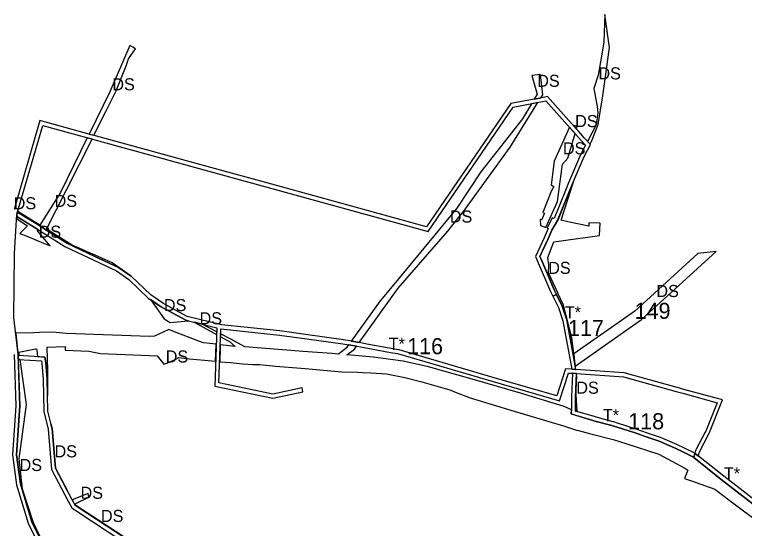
# Model space of a CAD drawing. Extents: x -477304 to -465641, y -1159113 to -1149285.
# Drawn here: x -471593 to -471049, y -1153715 to -1153332 of the extents above; entities that cross this region are included whole.
import ezdxf

# ---------------------------------------------------------------- set-up
doc = ezdxf.new("R2010")
doc.units = 0
for name, color, linetype in [('14', 7, 'Continuous'), ('35', 7, 'Continuous'), ('4', 7, 'Continuous'), ('60', 7, 'Continuous')]:
    doc.layers.add(name, color=color, linetype=linetype)

msp = doc.modelspace()

# ---------------------------------------------------------------- linework, layer by layer
at = {"layer": '14'}
for p, q in [((-471070.39, -1153508.62), (-471083.94, -1153510.15)), ((-471175.31, -1153593.86), (-471175.29, -1153593.96))]:
    msp.add_line(p, q, dxfattribs=at)
for points in [[(-471175.29, -1153593.96), (-471125.97, -1153559.31), (-471070.39, -1153508.62)], [(-471083.94, -1153510.15), (-471130.99, -1153553.06), (-471176.35, -1153584.93)], [(-471176.35, -1153584.93), (-471175.69, -1153590.63), (-471175.31, -1153593.86)]]:
    msp.add_lwpolyline(points, dxfattribs=at)
at = {"layer": '35'}
for p, q in [((-471153.26, -1153332.25), (-471153.87, -1153352.54)), ((-471504.57, -1153356.6), (-471506.78, -1153355.15)), ((-471502.61, -1153357.86), (-471504.57, -1153356.6)), ((-471153.87, -1153352.54), (-471155.75, -1153363.3)), ((-471507.84, -1153365.29), (-471502.61, -1153357.86)), ((-471509.71, -1153370.34), (-471507.84, -1153365.29)), ((-471155.75, -1153363.3), (-471158.23, -1153377.45)), ((-471517.12, -1153389.03), (-471509.71, -1153370.34)), ((-471201.13, -1153376.92), (-471207.63, -1153377.64)), ((-471199.47, -1153391.91), (-471201.13, -1153376.92)), ((-471158.23, -1153377.45), (-471161.5, -1153387.25)), ((-471524.62, -1153404.35), (-471517.12, -1153389.03)), ((-471161.5, -1153387.25), (-471158.95, -1153400.81)), ((-471200.93, -1153394.26), (-471199.47, -1153391.91)), ((-471158.17, -1153414.21), (-471154.66, -1153392.72)), ((-471223.64, -1153430.89), (-471203.08, -1153397.73)), ((-471207.77, -1153398.64), (-471214.42, -1153409.84)), ((-471203.08, -1153397.73), (-471207.77, -1153398.64)), ((-471533.59, -1153422.16), (-471524.62, -1153404.35)), ((-471158.56, -1153405.29), (-471159.57, -1153414.43)), ((-471158.95, -1153400.81), (-471158.56, -1153405.29)), ((-471214.42, -1153409.84), (-471245.64, -1153449.35)), ((-471179.62, -1153416.07), (-471190.85, -1153441.33)), ((-471175.29, -1153420.9), (-471179.62, -1153416.07)), ((-471173.71, -1153415.61), (-471176.9, -1153414.6)), ((-471174.28, -1153417.53), (-471173.71, -1153415.61)), ((-471159.57, -1153414.43), (-471166.1, -1153426.66)), ((-471162.56, -1153425.49), (-471158.17, -1153414.21)), ((-471180.7, -1153439.05), (-471175.29, -1153420.9)), ((-471538.53, -1153423.92), (-471558.53, -1153464.67)), ((-471554.05, -1153462.8), (-471534.97, -1153424.9)), ((-471534.97, -1153424.9), (-471538.53, -1153423.92)), ((-471166.1, -1153426.66), (-471164.23, -1153428.75)), ((-471164.23, -1153428.75), (-471162.56, -1153425.49)), ((-471259.06, -1153479.59), (-471223.64, -1153430.89)), ((-471190.85, -1153441.33), (-471193.1, -1153459.06)), ((-471245.64, -1153449.35), (-471263.3, -1153476.38)), ((-471193.1, -1153459.06), (-471191.15, -1153460.17)), ((-471185.8, -1153485.31), (-471176.64, -1153456.89)), ((-471558.53, -1153464.67), (-471573.79, -1153489.04)), ((-471568.84, -1153492.14), (-471554.05, -1153462.8)), ((-471192.84, -1153463.23), (-471199.39, -1153479.58)), ((-471191.15, -1153460.17), (-471192.84, -1153463.23)), ((-471197.19, -1153490.88), (-471188.35, -1153471.52)), ((-471590.35, -1153478.87), (-471590.48, -1153479.34)), ((-471573.79, -1153489.04), (-471590.35, -1153478.87)), ((-471263.3, -1153476.38), (-471304.47, -1153526.09)), ((-471261.88, -1153483.13), (-471259.06, -1153479.59)), ((-471198.19, -1153480.08), (-471200.35, -1153485.34)), ((-471199.39, -1153479.58), (-471198.19, -1153480.08)), ((-471591, -1153482.55), (-471591.11, -1153484.39)), ((-471591.11, -1153484.39), (-471583.17, -1153489.5)), ((-471581.05, -1153488.71), (-471591, -1153482.55)), ((-471270.21, -1153493.58), (-471261.88, -1153483.13)), ((-471200.35, -1153485.34), (-471201.46, -1153484.88)), ((-471201.46, -1153484.88), (-471201.19, -1153489.33)), ((-471188.38, -1153485.63), (-471192.58, -1153492.66)), ((-471188.02, -1153484.75), (-471188.38, -1153485.63)), ((-471180.84, -1153486.55), (-471185.8, -1153485.31)), ((-471165.11, -1153489.74), (-471180.84, -1153486.55)), ((-471583.17, -1153489.5), (-471588.75, -1153495.17)), ((-471578.21, -1153490.47), (-471581.05, -1153488.71)), ((-471575.38, -1153492.25), (-471578.21, -1153490.47)), ((-471575.65, -1153493.28), (-471575.38, -1153492.25)), ((-471563.06, -1153495.82), (-471568.84, -1153492.14)), ((-471201.19, -1153489.33), (-471197.19, -1153490.88)), ((-471165.07, -1153487.35), (-471165.11, -1153489.74)), ((-471156.76, -1153487.53), (-471165.07, -1153487.35)), ((-471157.24, -1153496.84), (-471156.76, -1153487.53)), ((-471588.75, -1153495.17), (-471584.16, -1153497.07)), ((-471584.16, -1153497.07), (-471571.1, -1153502.48)), ((-471566.24, -1153504.49), (-471575.65, -1153493.28)), ((-471306.99, -1153535.86), (-471270.21, -1153493.58)), ((-471192.58, -1153492.66), (-471195.75, -1153499.62)), ((-471191.32, -1153501.42), (-471157.24, -1153496.84)), ((-471571.1, -1153502.48), (-471566.24, -1153504.49)), ((-471195.75, -1153499.62), (-471199.01, -1153506.75)), ((-471195.66, -1153513.24), (-471191.32, -1153501.42)), ((-471199.01, -1153506.75), (-471199.12, -1153506.98)), ((-471519.92, -1153517.09), (-471530.34, -1153512.46)), ((-471194.82, -1153518.49), (-471195.66, -1153513.24)), ((-471515.1, -1153520.51), (-471519.92, -1153517.09)), ((-471195.1, -1153524.61), (-471194.82, -1153518.49)), ((-471515.43, -1153520.57), (-471505.82, -1153527.09)), ((-471505.82, -1153527.09), (-471515.1, -1153520.51)), ((-471336.16, -1153576.5), (-471306.99, -1153535.86)), ((-471484.13, -1153549.53), (-471491.47, -1153544.52)), ((-471491.47, -1153544.52), (-471481.37, -1153558.81)), ((-471320.48, -1153545.29), (-471342.04, -1153575.43)), ((-471463.31, -1153560.3), (-471465.24, -1153559.82)), ((-471453.1, -1153562.85), (-471458.88, -1153561.41)), ((-471458.88, -1153561.41), (-471442.28, -1153570.5)), ((-471442.21, -1153568.49), (-471453.1, -1153562.85)), ((-471477.72, -1153566.83), (-471482.16, -1153568.86)), ((-471473.7, -1153568.51), (-471477.72, -1153566.83)), ((-471455.45, -1153575.44), (-471473.7, -1153568.51)), ((-471442.28, -1153570.5), (-471442.21, -1153568.49)), ((-471591.55, -1153569.41), (-471591.83, -1153569.43)), ((-471591.83, -1153569.43), (-471590.72, -1153579.53)), ((-471578.22, -1153569.23), (-471591.55, -1153569.41)), ((-471574.11, -1153568.99), (-471578.22, -1153569.23)), ((-471564.11, -1153568.73), (-471574.11, -1153568.99)), ((-471488.44, -1153571.73), (-471492.17, -1153571.99)), ((-471482.16, -1153568.86), (-471488.44, -1153571.73)), ((-471439.26, -1153570.01), (-471439.33, -1153572.11)), ((-471439.33, -1153572.11), (-471432.63, -1153575.78)), ((-471431.66, -1153573.95), (-471439.26, -1153570.01)), ((-471421.37, -1153579.58), (-471431.66, -1153573.95)), ((-471452, -1153576.75), (-471455.45, -1153575.44)), ((-471442.53, -1153577.78), (-471452, -1153576.75)), ((-471442.97, -1153590.42), (-471442.53, -1153577.78)), ((-471439.54, -1153578.11), (-471439.64, -1153580.84)), ((-471428.45, -1153579.32), (-471439.54, -1153578.11)), ((-471432.63, -1153575.78), (-471428.45, -1153579.32)), ((-471343.97, -1153578.13), (-471346.01, -1153580.98)), ((-471339.68, -1153581.4), (-471338.1, -1153579.2)), ((-471590.72, -1153579.53), (-471590.45, -1153582.02)), ((-471590.45, -1153582.02), (-471590.11, -1153585.11)), ((-471589.41, -1153583.6), (-471577.2, -1153581.09)), ((-471589.04, -1153586.18), (-471589.41, -1153583.6)), ((-471577.2, -1153581.09), (-471576.29, -1153581.03)), ((-471576.29, -1153581.03), (-471576.17, -1153582.12)), ((-471576.17, -1153582.12), (-471575.62, -1153586.97)), ((-471568.43, -1153579.98), (-471555.04, -1153579.46)), ((-471568.08, -1153589.04), (-471568.43, -1153579.98)), ((-471555.04, -1153579.46), (-471554.94, -1153582.13)), ((-471554.94, -1153582.13), (-471537.39, -1153582.98)), ((-471537.39, -1153582.98), (-471528.59, -1153584.53)), ((-471528.59, -1153584.53), (-471486.48, -1153586.34)), ((-471439.64, -1153580.84), (-471439.98, -1153590.72)), ((-471380.68, -1153582.86), (-471421.37, -1153579.58)), ((-471351.53, -1153585.11), (-471356.21, -1153584.75)), ((-471346.01, -1153580.98), (-471351.53, -1153585.11)), ((-471345.28, -1153585.59), (-471339.68, -1153581.4)), ((-471590.11, -1153585.11), (-471590.07, -1153586.12)), ((-471590.07, -1153586.12), (-471589.04, -1153586.18)), ((-471588.61, -1153589.21), (-471589.96, -1153589.13)), ((-471583.88, -1153622.53), (-471588.61, -1153589.21)), ((-471575.62, -1153586.97), (-471570.07, -1153587.3)), ((-471568, -1153596.67), (-471568.08, -1153589.04)), ((-471486.48, -1153586.34), (-471482.43, -1153591.38)), ((-471478.59, -1153591.7), (-471473.22, -1153589.05)), ((-471473.22, -1153589.05), (-471470.42, -1153587.67)), ((-471470.42, -1153587.67), (-471468.44, -1153587.91)), ((-471468.44, -1153587.91), (-471465.15, -1153588.23)), ((-471465.15, -1153588.23), (-471442.97, -1153590.42)), ((-471339.25, -1153586.05), (-471345.28, -1153585.59)), ((-471325.69, -1153587.36), (-471339.25, -1153586.05)), ((-471176.89, -1153585.31), (-471175.31, -1153593.86)), ((-471482.43, -1153591.38), (-471481.55, -1153592.48)), ((-471481.55, -1153592.48), (-471478.59, -1153591.7)), ((-471422.87, -1153592.2), (-471418.94, -1153592.57)), ((-471418.94, -1153592.57), (-471415.32, -1153592.9)), ((-471415.32, -1153592.9), (-471414.51, -1153592.9)), ((-471405.47, -1153593.3), (-471398.45, -1153593.94)), ((-471567.92, -1153610.69), (-471568, -1153596.67)), ((-471337.21, -1153598.64), (-471333.54, -1153598.74)), ((-471333.54, -1153598.74), (-471327.39, -1153598.92)), ((-471327.39, -1153598.92), (-471315.85, -1153599.85)), ((-471215.99, -1153614.15), (-471251.89, -1153603.85)), ((-471174.44, -1153601.37), (-471174.96, -1153617.12)), ((-471567.99, -1153614.18), (-471567.92, -1153610.69)), ((-471568.15, -1153615.86), (-471567.99, -1153614.18)), ((-471183.59, -1153624.05), (-471215.99, -1153614.15)), ((-471174.96, -1153617.12), (-471175.11, -1153627.46)), ((-471173.82, -1153627.84), (-471174.45, -1153615.52)), ((-471228.08, -1153625.33), (-471192.33, -1153636.01)), ((-471178.13, -1153626.62), (-471183.59, -1153624.05)), ((-471178.26, -1153629.66), (-471178.13, -1153626.62)), ((-471175.11, -1153627.46), (-471173.82, -1153627.84)), ((-471174.55, -1153630.75), (-471178.26, -1153629.66)), ((-471159.57, -1153635.15), (-471174.55, -1153630.75)), ((-471564.59, -1153640.68), (-471565.66, -1153636.94)), ((-471565.66, -1153636.94), (-471564.82, -1153640.44)), ((-471192.33, -1153636.01), (-471183.91, -1153638.52)), ((-471183.91, -1153638.52), (-471174.22, -1153641.64)), ((-471562.25, -1153669.67), (-471564.59, -1153640.68)), ((-471164.59, -1153644.16), (-471147.02, -1153648.7)), ((-471147.02, -1153648.7), (-471137.68, -1153651.55)), ((-471137.68, -1153651.55), (-471112.96, -1153659.6)), ((-471078.02, -1153669.2), (-471086.84, -1153662.19)), ((-471553.94, -1153685.69), (-471562.25, -1153669.67)), ((-471091.36, -1153671.49), (-471093.87, -1153677.66)), ((-471093.87, -1153677.66), (-471088.67, -1153679.47)), ((-471088.67, -1153679.47), (-471071.33, -1153685.71)), ((-471553.32, -1153687), (-471553.94, -1153685.69)), ((-471071.33, -1153685.71), (-471059.91, -1153694.3)), ((-471537.84, -1153688.93), (-471549.78, -1153693.66)), ((-471548.12, -1153696.77), (-471537.36, -1153691.52)), ((-471537.36, -1153691.52), (-471537.84, -1153688.93)), ((-471549.78, -1153693.66), (-471548.12, -1153696.77)), ((-471511.99, -1153720.59), (-471547.83, -1153697.31)), ((-471547.83, -1153697.31), (-471547.69, -1153697.57)), ((-471059.91, -1153694.3), (-471032.64, -1153714.82)), ((-471558.34, -1153753.04), (-471578.48, -1153710.75))]:
    msp.add_line(p, q, dxfattribs=at)
for points in [[(-471154.66, -1153392.72), (-471149.87, -1153356.83), (-471153.26, -1153332.25)], [(-471506.78, -1153355.15), (-471521.74, -1153389.71), (-471537.18, -1153421.18)], [(-471207.63, -1153377.64), (-471203.49, -1153391.44), (-471205.72, -1153395.19)], [(-471205.72, -1153395.19), (-471201.53, -1153394.38), (-471200.93, -1153394.26)], [(-471176.9, -1153414.6), (-471175.99, -1153415.63), (-471174.28, -1153417.53)], [(-471537.18, -1153421.18), (-471536.3, -1153421.42), (-471533.59, -1153422.16)], [(-471188.35, -1153471.52), (-471184.67, -1153443.61), (-471180.7, -1153439.05)], [(-471176.64, -1153456.89), (-471177.43, -1153458.78), (-471179.72, -1153464.27), (-471188.02, -1153484.75)], [(-471590.48, -1153479.34), (-471576.62, -1153487.93), (-471568.23, -1153493.2), (-471562.91, -1153496.55), (-471556.64, -1153500.5), (-471553.72, -1153502.34), (-471532.82, -1153512.29), (-471515.43, -1153520.57)], [(-471530.34, -1153512.46), (-471549.69, -1153503.87), (-471563.06, -1153495.82)], [(-471199.12, -1153506.98), (-471201.58, -1153512.37), (-471200.75, -1153514.29), (-471190.89, -1153537.26), (-471189.19, -1153540.74)], [(-471187.91, -1153540.12), (-471188.18, -1153539.53), (-471195.1, -1153524.61)], [(-471304.47, -1153526.09), (-471316.58, -1153540.62), (-471320.48, -1153545.29)], [(-471189.19, -1153540.74), (-471185.02, -1153549.35), (-471181.64, -1153559.49), (-471176.89, -1153585.31)], [(-471176.35, -1153584.93), (-471177.79, -1153572.61), (-471183.99, -1153548.58), (-471187.91, -1153540.12)], [(-471465.24, -1153559.82), (-471484.01, -1153549.63), (-471484.13, -1153549.53)], [(-471481.37, -1153558.81), (-471476.72, -1153561.65), (-471463.31, -1153560.3)], [(-471492.17, -1153571.99), (-471554.18, -1153569.65), (-471564.11, -1153568.73)], [(-471338.1, -1153579.2), (-471343.75, -1153578.17), (-471343.97, -1153578.13)], [(-471342.04, -1153575.43), (-471341.63, -1153575.51), (-471336.16, -1153576.5)], [(-471356.21, -1153584.75), (-471378.13, -1153583.06), (-471380.68, -1153582.86)], [(-471589.96, -1153589.13), (-471588.75, -1153623.57), (-471591.27, -1153660.08), (-471588.26, -1153681.79), (-471579.89, -1153709.91), (-471557.48, -1153755.17)], [(-471570.07, -1153587.3), (-471569.49, -1153591.61), (-471568.41, -1153603.49), (-471568.15, -1153615.86)], [(-471251.89, -1153603.85), (-471284.42, -1153594.65), (-471303.31, -1153590.35), (-471325.69, -1153587.36)], [(-471175.31, -1153593.86), (-471175.69, -1153590.63), (-471176.35, -1153584.93)], [(-471439.98, -1153590.72), (-471439.33, -1153590.78), (-471431.82, -1153591.35), (-471422.87, -1153592.2)], [(-471414.51, -1153592.9), (-471410.01, -1153592.89), (-471405.47, -1153593.3)], [(-471398.45, -1153593.94), (-471379.39, -1153595.66), (-471376.33, -1153595.92)], [(-471376.33, -1153595.92), (-471349.03, -1153598.31), (-471337.21, -1153598.64)], [(-471315.85, -1153599.85), (-471302.08, -1153602.43), (-471289.45, -1153605.83), (-471268.75, -1153611.78)], [(-471174.45, -1153615.52), (-471174.34, -1153602.22), (-471174.44, -1153601.37)], [(-471268.75, -1153611.78), (-471265.26, -1153613.13), (-471253.48, -1153617.65), (-471233.99, -1153623.54), (-471228.08, -1153625.33)], [(-471578.48, -1153710.75), (-471586.74, -1153685.53), (-471589.38, -1153663.17), (-471583.88, -1153622.53)], [(-471086.84, -1153662.19), (-471087.49, -1153661.67), (-471087.7, -1153661.51), (-471094.68, -1153658.13), (-471100.89, -1153655.14), (-471112.75, -1153650.03), (-471122.39, -1153646.69), (-471130.7, -1153643.81), (-471144.79, -1153639.28), (-471147.4, -1153638.45), (-471147.97, -1153638.27), (-471159.57, -1153635.15)], [(-471564.82, -1153640.44), (-471562.33, -1153670.06), (-471553.32, -1153687)], [(-471174.22, -1153641.64), (-471172.85, -1153642.08), (-471164.59, -1153644.16)], [(-471112.96, -1153659.6), (-471093.61, -1153669.94), (-471091.36, -1153671.49)], [(-471022.56, -1153711.6), (-471028.57, -1153707.74), (-471066.5, -1153678.36), (-471078.02, -1153669.2)], [(-471547.69, -1153697.57), (-471545.36, -1153699.1), (-471510.88, -1153721.69), (-471503.72, -1153722.88)]]:
    msp.add_lwpolyline(points, dxfattribs=at)
at = {"layer": '4'}
for p, q in [((-471590.89, -1153480.85), (-471591, -1153482.55)), ((-471590.89, -1153480.76), (-471590.89, -1153480.85)), ((-471192.58, -1153492.66), (-471188.38, -1153485.63)), ((-471195.38, -1153491.58), (-471198.48, -1153498.37)), ((-471195.75, -1153499.62), (-471192.58, -1153492.66)), ((-471189.19, -1153540.74), (-471191.89, -1153542.05)), ((-471191.89, -1153542.05), (-471189.19, -1153540.74)), ((-471191.89, -1153542.05), (-471187.8, -1153550.48)), ((-471438.61, -1153563.36), (-471464.14, -1153557.01)), ((-471465.24, -1153559.82), (-471442.11, -1153565.58)), ((-471439.13, -1153566.33), (-471395.52, -1153570.85)), ((-471395.21, -1153567.86), (-471438.61, -1153563.36)), ((-471590.07, -1153586.12), (-471589.96, -1153589.13)), ((-471175.31, -1153593.86), (-471176.89, -1153585.31)), ((-471174.82, -1153596.56), (-471175.31, -1153593.86)), ((-471182.54, -1153596.05), (-471188.94, -1153616.26)), ((-471180.39, -1153599.2), (-471177.37, -1153599.39)), ((-471177.9, -1153596.35), (-471175, -1153596.54)), ((-471177.37, -1153599.39), (-471174.38, -1153599.59)), ((-471174.38, -1153599.59), (-471177.37, -1153599.39)), ((-471175, -1153596.54), (-471174.82, -1153596.56)), ((-471174.96, -1153617.12), (-471174.38, -1153599.59)), ((-471174.38, -1153599.59), (-471139.38, -1153601.89)), ((-471378.05, -1153613.08), (-471378.68, -1153610.15)), ((-471175.11, -1153627.46), (-471174.96, -1153617.12)), ((-471178.26, -1153629.66), (-471159.57, -1153635.15)), ((-471086.38, -1153660.19), (-471086.84, -1153662.19)), ((-471086.84, -1153662.19), (-471086.38, -1153660.19)), ((-471086.1, -1153658.95), (-471086.38, -1153660.19)), ((-471086.38, -1153660.19), (-471086.1, -1153658.95)), ((-471085.63, -1153659.32), (-471086.1, -1153658.95)), ((-471083.49, -1153661.02), (-471085.63, -1153659.32))]:
    msp.add_line(p, q, dxfattribs=at)
for points in [[(-471163.97, -1153429.04), (-471168.57, -1153423.91), (-471171.39, -1153420.76), (-471172.87, -1153419.1), (-471175.99, -1153415.63), (-471195.98, -1153393.3), (-471197.92, -1153393.68), (-471201.53, -1153394.38), (-471223.27, -1153398.58), (-471286, -1153490.27), (-471401.07, -1153458.62), (-471436.72, -1153448.81), (-471532.55, -1153422.45), (-471536.3, -1153421.42), (-471573.82, -1153411.1), (-471593.07, -1153477.49)], [(-471518.29, -1153956.42), (-471540.25, -1153885.85), (-471527.35, -1153830.76), (-471528.58, -1153824.83), (-471547.09, -1153784.31), (-471550.09, -1153776.39), (-471556.65, -1153756.83), (-471579.89, -1153709.91), (-471588.26, -1153681.79), (-471591.27, -1153660.08), (-471588.75, -1153623.57), (-471590.11, -1153585.11), (-471593.12, -1153557.74), (-471592.67, -1153510.14), (-471590.89, -1153480.85), (-471590.89, -1153480.76), (-471571.76, -1153414.78), (-471284.73, -1153493.73), (-471221.49, -1153401.29), (-471197.08, -1153396.57), (-471170.8, -1153425.91), (-471167.61, -1153429.48)], [(-471167.61, -1153429.48), (-471171.44, -1153436.65), (-471180.2, -1153457.63), (-471182.49, -1153463.13), (-471190.96, -1153484.02)], [(-471188.38, -1153485.63), (-471179.72, -1153464.27), (-471177.43, -1153458.78), (-471168.73, -1153437.94), (-471163.97, -1153429.04)], [(-471515.43, -1153520.57), (-471532.82, -1153512.29), (-471553.72, -1153502.34), (-471556.64, -1153500.5), (-471562.91, -1153496.55), (-471568.23, -1153493.2), (-471576.62, -1153487.93), (-471590.48, -1153479.34), (-471590.89, -1153480.76)], [(-471591, -1153482.55), (-471578.21, -1153490.47), (-471574.01, -1153493.12), (-471555.17, -1153504.97), (-471516.92, -1153523.18)], [(-471190.96, -1153484.02), (-471192.48, -1153483.64), (-471196.13, -1153491.29), (-471195.38, -1153491.58)], [(-471198.48, -1153498.37), (-471204.86, -1153512.33), (-471203.51, -1153515.47), (-471193.62, -1153538.51), (-471191.89, -1153542.05)], [(-471189.19, -1153540.74), (-471190.89, -1153537.26), (-471200.75, -1153514.29), (-471201.58, -1153512.37), (-471195.75, -1153499.62)], [(-471516.92, -1153523.18), (-471507.71, -1153529.43), (-471493.15, -1153543.37), (-471484.13, -1153549.53)], [(-471482.27, -1153547.17), (-471491.25, -1153541.03), (-471505.82, -1153527.09), (-471515.43, -1153520.57)], [(-471176.89, -1153585.31), (-471181.64, -1153559.49), (-471185.02, -1153549.35), (-471189.19, -1153540.74)], [(-471484.13, -1153549.53), (-471484.01, -1153549.63), (-471465.24, -1153559.82)], [(-471464.14, -1153557.01), (-471467.3, -1153555.29), (-471482.27, -1153547.17)], [(-471187.8, -1153550.48), (-471184.55, -1153560.24), (-471177.9, -1153596.35)], [(-471442.11, -1153565.58), (-471443.61, -1153609), (-471400.38, -1153617.93), (-471378.05, -1153613.08)], [(-471378.68, -1153610.15), (-471400.39, -1153614.87), (-471440.53, -1153606.58), (-471439.13, -1153566.33)], [(-471188.94, -1153616.26), (-471235.56, -1153602.63), (-471306.4, -1153581.92), (-471306.81, -1153581.8), (-471330.3, -1153577.56), (-471335.95, -1153576.53), (-471341.63, -1153575.51), (-471347.71, -1153574.41), (-471374.31, -1153570.74), (-471395.17, -1153567.87), (-471395.21, -1153567.86)], [(-471395.52, -1153570.85), (-471375.15, -1153573.66), (-471348.18, -1153577.37), (-471343.75, -1153578.17), (-471337.99, -1153579.22), (-471332.35, -1153580.23), (-471312.85, -1153583.76), (-471307.5, -1153584.72), (-471236.4, -1153605.51), (-471186.96, -1153619.97), (-471180.39, -1153599.2)], [(-471593.1, -1153585.33), (-471591.75, -1153623.52), (-471594.28, -1153660.18), (-471591.2, -1153682.43), (-471582.69, -1153711.01), (-471559.43, -1153757.98), (-471552.92, -1153777.4), (-471549.86, -1153785.47), (-471531.45, -1153825.77), (-471530.42, -1153830.72), (-471543.35, -1153885.97), (-471540.91, -1153893.83), (-471539.22, -1153899.26), (-471538.44, -1153901.74), (-471522.52, -1153952.94)], [(-471443.2, -1153802.96), (-471447.93, -1153796.05), (-471486.59, -1153739.57), (-471497.31, -1153723.94), (-471510.88, -1153721.69), (-471545.36, -1153699.1), (-471547.69, -1153697.57), (-471550.03, -1153693.18), (-471562.33, -1153670.06), (-471564.82, -1153640.44), (-471567.91, -1153627.54), (-471568.41, -1153603.49), (-471569.49, -1153591.61), (-471570.07, -1153587.3), (-471590.07, -1153586.12)], [(-471589.96, -1153589.13), (-471572.71, -1153590.15), (-471572.47, -1153591.95), (-471571.41, -1153603.66), (-471570.9, -1153627.92), (-471567.79, -1153640.92), (-471565.27, -1153670.93), (-471552.68, -1153694.59), (-471549.98, -1153699.66), (-471547.01, -1153701.61), (-471511.99, -1153724.55), (-471499.06, -1153726.69), (-471489.07, -1153741.27), (-471450.41, -1153797.74), (-471445.68, -1153804.65)], [(-471083.49, -1153661.02), (-471082.8, -1153657.97), (-471075.7, -1153644.56), (-471075.27, -1153643.48), (-471065.56, -1153619.23), (-471094.33, -1153611.37), (-471099.33, -1153609.95), (-471138.87, -1153598.92), (-471174.82, -1153596.56), (-471175, -1153596.54), (-471177.9, -1153596.35), (-471182.54, -1153596.05)], [(-471177.37, -1153599.39), (-471177.96, -1153617.05), (-471178.08, -1153625.46), (-471178.26, -1153629.66)], [(-471139.38, -1153601.89), (-471100.14, -1153612.84), (-471095.14, -1153614.26), (-471069.6, -1153621.24), (-471078.06, -1153642.37), (-471078.43, -1153643.3), (-471085.64, -1153656.92), (-471086.1, -1153658.95)], [(-471086.1, -1153658.95), (-471093.38, -1153655.43), (-471099.64, -1153652.41), (-471111.66, -1153647.23), (-471121.43, -1153643.85), (-471129.85, -1153640.93), (-471143.86, -1153636.43), (-471146.55, -1153635.57), (-471147.12, -1153635.39), (-471158.75, -1153632.26), (-471161, -1153631.6), (-471175.11, -1153627.46)], [(-471159.57, -1153635.15), (-471147.97, -1153638.27), (-471147.4, -1153638.45), (-471144.79, -1153639.28), (-471130.7, -1153643.81), (-471122.39, -1153646.69), (-471112.75, -1153650.03), (-471100.89, -1153655.14), (-471094.68, -1153658.13), (-471087.7, -1153661.51), (-471087.49, -1153661.67), (-471086.84, -1153662.19)], [(-471086.1, -1153658.95), (-471085.63, -1153659.32), (-471083.49, -1153661.02)], [(-471086.84, -1153662.19), (-471066.5, -1153678.36), (-471028.57, -1153707.74), (-471016.48, -1153715.49)], [(-471026.84, -1153705.29), (-471064.65, -1153676), (-471083.49, -1153661.02)]]:
    msp.add_lwpolyline(points, dxfattribs=at)

# ---------------------------------------------------------------- texts
at = {"layer": '14'}
msp.add_text('DS', height=9, dxfattribs=at).set_placement((-471114.85, -1153542.58))
at = {"layer": '35'}
for p in [(-471157.99, -1153380.5), (-471203.55, -1153386.05), (-471519.9, -1153388.66), (-471175.31, -1153416.06), (-471184.39, -1153436.34), (-471593.35, -1153477.25), (-471562.88, -1153475.5), (-471268.62, -1153487.12), (-471574.72, -1153498.4), (-471195.37, -1153525.37), (-471481.54, -1153553.08), (-471454.94, -1153562.91), (-471480.16, -1153591.34), (-471174.46, -1153614.6), (-471562.94, -1153661.97), (-471588.96, -1153672.15), (-471543.57, -1153692.85), (-471528.37, -1153710.09)]:
    msp.add_text('DS', height=9, dxfattribs=at).set_placement(p)
at = {"layer": '4'}
for p in [(-471183.01, -1153558.41), (-471314.13, -1153581.93), (-471154.69, -1153635.07), (-471064.58, -1153678.44)]:
    msp.add_text('T*', height=9, dxfattribs=at).set_placement(p)
at = {"layer": '60'}
for s, p in [('149', (-471131.08, -1153558.85)), ('117', (-471180.7, -1153571.71)), ('116', (-471300.44, -1153585.17)), ('118', (-471135.84, -1153641.07))]:
    msp.add_text(s, height=12, dxfattribs=at).set_placement(p)

doc.saveas('drawing.dxf')
